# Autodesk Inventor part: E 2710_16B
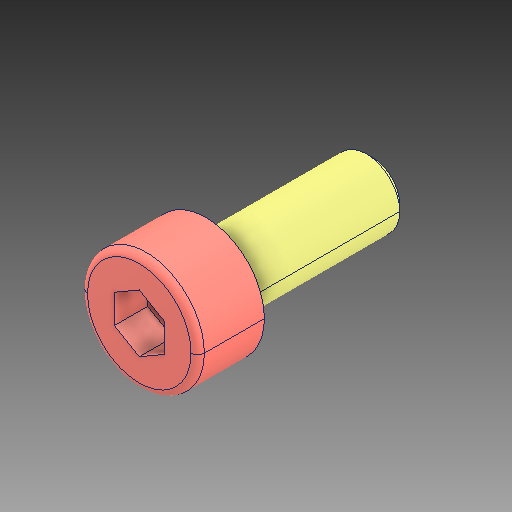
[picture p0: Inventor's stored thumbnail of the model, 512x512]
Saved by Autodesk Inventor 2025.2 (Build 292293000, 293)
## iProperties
Created: 2025-05
Part Number: E 2710_16B
Material: Všeobecné
Document SubType Name: Modeling
Designer: Patrik
Density: 1 g/cm^3
Appearance: Výchozí
Mass: 0.262428 g
Surface Area: 3.0455 cm^2
Volume: 0.262428 cm^3
Author: Patrik
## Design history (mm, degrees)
feature "Base1"
node "Těleso1"
